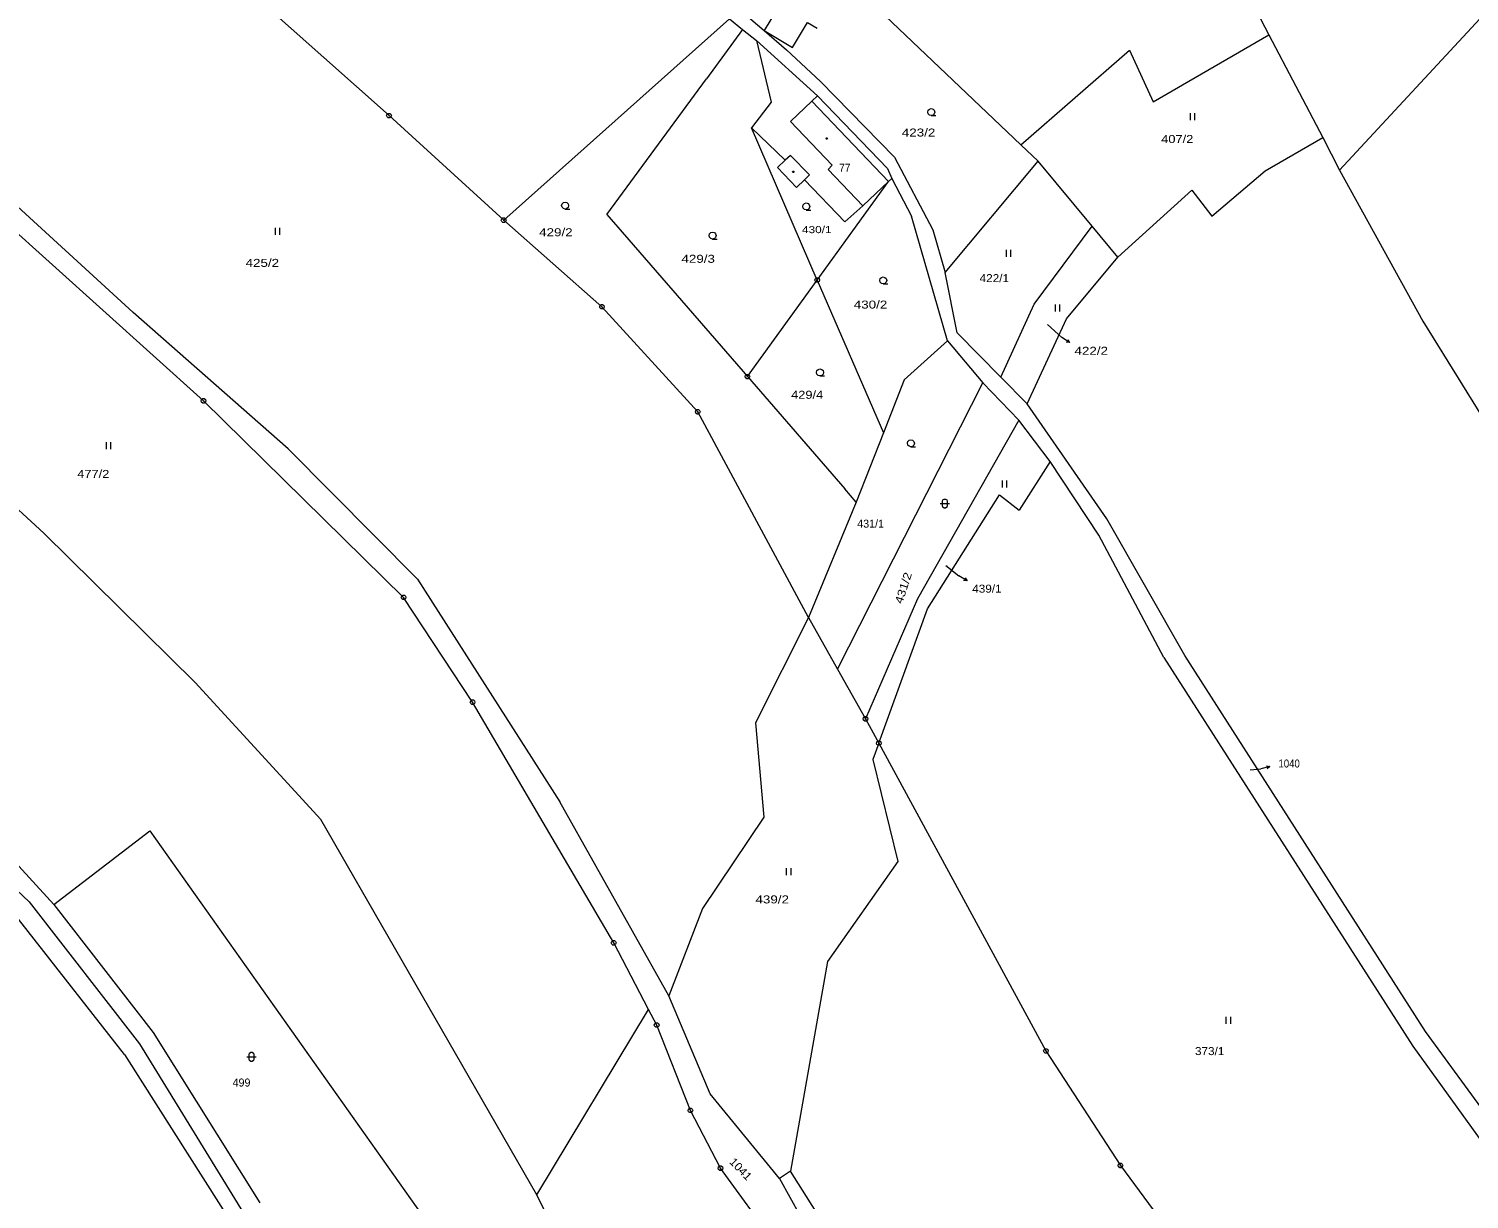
# Model space of a CAD drawing. Extents: x -687390 to -684106, y -954833 to -951648.
# Drawn here: x -686675.9 to -686369.8, y -953064 to -952815.4 of the extents above; entities that cross this region are included whole.
import ezdxf

# ---------------------------------------------------------------- set-up
doc = ezdxf.new("R2010")
doc.units = 0
doc.header["$LTSCALE"] = 0.68
for name, color, linetype, lineweight in [('1', 7, 'Continuous', 13), ('3', 7, 'Continuous', 13), ('4', 7, 'Continuous', 13), ('5', 7, 'Continuous', 13), ('7', 7, 'Continuous', 13), ('8', 7, 'Continuous', 13)]:
    doc.layers.add(name, color=color, linetype=linetype, lineweight=lineweight)
doc.layers.add('2', color=7, linetype='Continuous')

msp = doc.modelspace()

# ---------------------------------------------------------------- linework, layer by layer
at = {"layer": '1'}
for p, q in [((-686509.81, -952799.39), (-686519.6, -952815.68)), ((-686524.22, -952815.52), (-686531.9, -952825.99)), ((-686519.6, -952815.68), (-686514.85, -952819.8)), ((-686521.24, -952817.86), (-686508.32, -952829.6)), ((-686507.68, -952826.56), (-686514.85, -952819.8)), ((-686553.05, -952854.83), (-686531.9, -952825.99)), ((-686508.33, -952868.74), (-686522.33, -952836.4)), ((-686693.09, -952839.54), (-686653.72, -952875.6)), ((-686516.76, -952844.8), (-686515.14, -952843.29)), ((-686511.05, -952847.43), (-686502.5, -952856.37)), ((-686498.67, -952852.97), (-686493.17, -952847.8)), ((-686493.17, -952847.8), (-686492.46, -952847.13)), ((-686492.46, -952847.13), (-686488.32, -952855.19)), ((-686502.5, -952856.37), (-686498.67, -952852.97)), ((-686553.05, -952854.83), (-686523.18, -952889.26)), ((-686462.22, -952873.88), (-686449.89, -952857.3)), ((-686672.7, -952922.52), (-686738.23, -952862.13)), ((-686508.33, -952868.74), (-686494.26, -952901.21)), ((-686469.32, -952889.38), (-686462.22, -952873.88)), ((-686620.74, -952904.63), (-686653.72, -952875.6)), ((-686523.18, -952889.26), (-686502.49, -952913.07)), ((-686504.01, -952951.43), (-686473.18, -952890.6)), ((-686489.85, -952889.96), (-686494.26, -952901.21)), ((-686494.26, -952901.21), (-686500.04, -952915.93)), ((-686593.31, -952932.3), (-686620.74, -952904.63)), ((-686458.83, -952907.29), (-686465.43, -952917.64)), ((-686500.04, -952915.93), (-686502.49, -952913.07)), ((-686469.61, -952914.35), (-686465.43, -952917.64)), ((-686672.7, -952922.52), (-686640.52, -952954.27)), ((-686434.72, -952948.96), (-686448.54, -952922.97)), ((-686593.31, -952932.3), (-686563.07, -952979.58)), ((-686434.72, -952948.96), (-686381.78, -953031.54)), ((-686613.86, -952983.34), (-686640.52, -952954.27)), ((-686670.54, -953001.44), (-686696.66, -952973)), ((-686539.88, -953020.85), (-686563.07, -952979.58)), ((-686670.54, -953001.44), (-686650.19, -952985.77)), ((-686650.19, -952985.77), (-686584.91, -953077.81)), ((-686567.94, -953063.1), (-686544.19, -953023.73)), ((-686320.99, -953107.93), (-686379.12, -953028.38)), ((-686381.78, -953031.54), (-686358.91, -953063.3)), ((-686655.57, -953033.26), (-686630.63, -953072.46)), ((-686495.55, -953087.28), (-686514, -953058.06)), ((-686516.33, -953059.65), (-686511.96, -953067.55))]:
    msp.add_line(p, q, dxfattribs=at)
for points in [[(-686646.49, -952707.88), (-686543.29, -952795.55), (-686519.6, -952815.68)], [(-686695.55, -952748.71), (-686654.22, -952784.95), (-686599.33, -952833.8), (-686574.97, -952856.02)], [(-686397.36, -952845.42), (-686365.69, -952811.22), (-686368.52, -952807.17), (-686369.02, -952794.4), (-686360.88, -952785.09), (-686366.08, -952768.4)], [(-686453.59, -952771.6), (-686414.98, -952811.6), (-686412.39, -952816.64)], [(-686551.59, -953009.58), (-686581.57, -952958.44), (-686596.23, -952936.18), (-686638.74, -952894.41), (-686702.99, -952836.61), (-686720, -952820.76), (-686730.92, -952811.22), (-686750.22, -952797.63), (-686771.71, -952798.21), (-686764.24, -952793.45), (-686750.29, -952793.68), (-686755.86, -952788.44)], [(-686500.04, -952915.93), (-686510.19, -952940.46), (-686533.73, -952896.74), (-686554.09, -952874.42), (-686574.97, -952856.02), (-686527, -952813.23), (-686524.22, -952815.52)], [(-686519.6, -952815.68), (-686513.58, -952819.3), (-686510.38, -952813.98), (-686508.39, -952815.18)], [(-686461.39, -952843.48), (-686465.11, -952839.97), (-686493.92, -952812.62)], [(-686524.22, -952815.52), (-686521.24, -952817.86), (-686518.14, -952830.94), (-686522.33, -952836.4), (-686515.14, -952843.29)], [(-686465.11, -952839.97), (-686442.01, -952819.9), (-686436.94, -952830.9), (-686412.39, -952816.64), (-686400.9, -952838.46)], [(-686507.68, -952826.56), (-686491.9, -952842.65), (-686483.77, -952858.03), (-686481.13, -952867.13)], [(-686508.32, -952829.6), (-686493.42, -952845.05), (-686492.46, -952847.13)], [(-686444.44, -952863.85), (-686428.72, -952849.66), (-686424.51, -952855.14), (-686413.17, -952845.53), (-686400.9, -952838.46), (-686397.36, -952845.42)], [(-686516.76, -952844.8), (-686512.77, -952849.07), (-686511.05, -952847.43)], [(-686478.6, -952879.92), (-686481.13, -952867.13), (-686461.39, -952843.48)], [(-686444.44, -952863.85), (-686449.89, -952857.3), (-686461.39, -952843.48)], [(-686523.18, -952889.26), (-686508.33, -952868.74), (-686493.17, -952847.8)], [(-686397.36, -952845.42), (-686379.65, -952877.44), (-686354.39, -952918.28)], [(-686489.85, -952889.96), (-686480.65, -952881.64), (-686488.32, -952855.19)], [(-686379.12, -953028.38), (-686430.21, -952948.54), (-686446.81, -952919.48), (-686463.76, -952895.04), (-686455.41, -952876.97), (-686444.44, -952863.85)], [(-686463.76, -952895.04), (-686469.32, -952889.38), (-686478.6, -952879.92)], [(-686480.65, -952881.64), (-686473.18, -952890.6), (-686465.48, -952898.5)], [(-686465.48, -952898.5), (-686487.06, -952936.49), (-686498.08, -952961.98)], [(-686448.54, -952922.97), (-686458.83, -952907.29), (-686465.48, -952898.5)], [(-686495.25, -952967.14), (-686484.95, -952938.57), (-686469.61, -952914.35)], [(-686744.67, -952933.19), (-686724.45, -952954.91), (-686675.78, -953000.89), (-686652.38, -953031), (-686618.65, -953085.9), (-686604.76, -953115.49), (-686593.43, -953134.24)], [(-686510.19, -952940.46), (-686521.45, -952962.85), (-686519.67, -952982.87), (-686532.76, -953002.28), (-686539.88, -953020.85)], [(-686510.19, -952940.46), (-686504.01, -952951.43), (-686498.08, -952961.98)], [(-686655.57, -953033.26), (-686679.35, -953002.91), (-686725.64, -952957.15)], [(-686498.08, -952961.98), (-686495.25, -952967.14), (-686459.74, -953032.55), (-686443.92, -953056.89), (-686425.27, -953082.18), (-686401.26, -953112.58), (-686367.6, -953151.83), (-686353.01, -953164.57)], [(-686495.25, -952967.14), (-686496.51, -952970.6), (-686491.22, -952992.29), (-686506.18, -953013.5), (-686514, -953058.06), (-686516.33, -953059.65), (-686531.12, -953041.67), (-686539.88, -953020.85)], [(-686566.44, -953066.15), (-686567.94, -953063.1), (-686613.86, -952983.34)], [(-686670.54, -953001.44), (-686649.45, -953028.64), (-686626.76, -953064.78)], [(-686542.46, -953027.04), (-686544.19, -953023.73), (-686551.59, -953009.58)], [(-686252.58, -953389.33), (-686292.75, -953324.92), (-686302.57, -953310.07), (-686336.76, -953268.21), (-686375.07, -953232.58), (-686400.17, -953211.88), (-686416.48, -953192.52), (-686437.08, -953164.4), (-686477, -953119.5), (-686503.23, -953091.93), (-686517.39, -953073.32), (-686528.9, -953057.45), (-686535.29, -953045.19), (-686542.46, -953027.04)]]:
    msp.add_lwpolyline(points, dxfattribs=at)
at = {"layer": '3'}
for p, q in [((-686429.1, -952833.24), (-686429.1, -952834.74)), ((-686428.1, -952834.74), (-686428.1, -952833.24)), ((-686623.55, -952857.63), (-686623.55, -952859.13)), ((-686622.55, -952859.13), (-686622.55, -952857.63)), ((-686468.22, -952862.28), (-686468.22, -952863.78)), ((-686467.22, -952863.78), (-686467.22, -952862.28)), ((-686457.81, -952873.93), (-686457.81, -952875.43)), ((-686456.81, -952875.43), (-686456.81, -952873.93)), ((-686659.44, -952903.17), (-686659.44, -952904.67)), ((-686658.44, -952904.67), (-686658.44, -952903.17)), ((-686469.03, -952911.31), (-686469.03, -952912.81)), ((-686468.03, -952912.81), (-686468.03, -952911.31)), ((-686514.92, -952993.7), (-686514.92, -952995.2)), ((-686513.92, -952995.2), (-686513.92, -952993.7)), ((-686421.49, -953025.3), (-686421.49, -953026.8)), ((-686420.49, -953026.8), (-686420.49, -953025.3))]:
    msp.add_line(p, q, dxfattribs=at)
for points in [[(-686484.1, -952833.78), (-686484.48, -952833.68), (-686484.75, -952833.41), (-686484.85, -952833.04), (-686484.75, -952832.67), (-686484.48, -952832.4), (-686484.11, -952832.3), (-686483.74, -952832.4), (-686483.47, -952832.67), (-686483.37, -952833.05), (-686483.47, -952833.43), (-686483.74, -952833.7), (-686484.12, -952833.8), (-686483.12, -952833.8)], [(-686561.91, -952853.64), (-686562.29, -952853.54), (-686562.56, -952853.27), (-686562.66, -952852.9), (-686562.56, -952852.53), (-686562.29, -952852.26), (-686561.92, -952852.16), (-686561.55, -952852.26), (-686561.28, -952852.53), (-686561.18, -952852.91), (-686561.28, -952853.29), (-686561.55, -952853.56), (-686561.93, -952853.66), (-686560.93, -952853.66)], [(-686510.66, -952853.84), (-686511.04, -952853.74), (-686511.31, -952853.47), (-686511.41, -952853.1), (-686511.31, -952852.73), (-686511.04, -952852.46), (-686510.67, -952852.36), (-686510.3, -952852.46), (-686510.03, -952852.73), (-686509.93, -952853.11), (-686510.03, -952853.49), (-686510.3, -952853.76), (-686510.68, -952853.86), (-686509.68, -952853.86)], [(-686530.57, -952860.02), (-686530.95, -952859.92), (-686531.22, -952859.65), (-686531.32, -952859.28), (-686531.22, -952858.91), (-686530.95, -952858.64), (-686530.58, -952858.54), (-686530.21, -952858.64), (-686529.94, -952858.91), (-686529.84, -952859.29), (-686529.94, -952859.67), (-686530.21, -952859.94), (-686530.59, -952860.04), (-686529.59, -952860.04)], [(-686494.31, -952869.55), (-686494.69, -952869.45), (-686494.96, -952869.18), (-686495.06, -952868.81), (-686494.96, -952868.44), (-686494.69, -952868.17), (-686494.32, -952868.07), (-686493.95, -952868.17), (-686493.68, -952868.44), (-686493.58, -952868.82), (-686493.68, -952869.2), (-686493.95, -952869.47), (-686494.33, -952869.57), (-686493.33, -952869.57)], [(-686507.75, -952889.09), (-686508.13, -952888.99), (-686508.4, -952888.72), (-686508.5, -952888.35), (-686508.4, -952887.98), (-686508.13, -952887.71), (-686507.76, -952887.61), (-686507.39, -952887.71), (-686507.12, -952887.98), (-686507.02, -952888.36), (-686507.12, -952888.74), (-686507.39, -952889.01), (-686507.77, -952889.11), (-686506.77, -952889.11)], [(-686488.43, -952904.16), (-686488.81, -952904.06), (-686489.08, -952903.79), (-686489.18, -952903.42), (-686489.08, -952903.05), (-686488.81, -952902.78), (-686488.44, -952902.68), (-686488.07, -952902.78), (-686487.8, -952903.05), (-686487.7, -952903.43), (-686487.8, -952903.81), (-686488.07, -952904.08), (-686488.45, -952904.18), (-686487.45, -952904.18)], [(-686482.25, -952916.23), (-686480.98, -952916.23), (-686480.25, -952916.23)], [(-686629.56, -953033.8), (-686628.29, -953033.8), (-686627.56, -953033.8)]]:
    msp.add_lwpolyline(points, dxfattribs=at)
for points in [[(-686481.75, -952915.73), (-686481.65, -952915.44), (-686481.4, -952915.26), (-686481.09, -952915.26), (-686480.84, -952915.44), (-686480.74, -952915.73), (-686480.74, -952916.73), (-686480.84, -952917.02), (-686481.09, -952917.2), (-686481.4, -952917.2), (-686481.65, -952917.02), (-686481.75, -952916.73)], [(-686629.06, -953033.3), (-686628.96, -953033.01), (-686628.71, -953032.83), (-686628.4, -953032.83), (-686628.15, -953033.01), (-686628.05, -953033.3), (-686628.05, -953034.3), (-686628.15, -953034.59), (-686628.4, -953034.77), (-686628.71, -953034.77), (-686628.96, -953034.59), (-686629.06, -953034.3)]]:
    msp.add_lwpolyline(points, close=True, dxfattribs=at)
at = {"layer": '4'}
for p, q in [((-686509.46, -952830.7), (-686514.01, -952835.05)), ((-686508.32, -952829.6), (-686509.46, -952830.7)), ((-686493.17, -952847.8), (-686509.46, -952830.7)), ((-686514.01, -952835.05), (-686505.15, -952844.35)), ((-686511.05, -952847.43), (-686509.99, -952846.41))]:
    msp.add_line(p, q, dxfattribs=at)
for points in [[(-686509.99, -952846.41), (-686514.01, -952842.24), (-686515.14, -952843.29)], [(-686505.15, -952844.35), (-686506.04, -952845.22), (-686498.67, -952852.97)]]:
    msp.add_lwpolyline(points, dxfattribs=at)
at = {"layer": '5'}
for points in [[(-686506.23, -952838.51), (-686506.14, -952838.66), (-686506.23, -952838.81), (-686506.41, -952838.81), (-686506.5, -952838.66), (-686506.41, -952838.51)], [(-686513.34, -952845.57), (-686513.25, -952845.72), (-686513.34, -952845.87), (-686513.52, -952845.87), (-686513.61, -952845.72), (-686513.52, -952845.57)]]:
    msp.add_lwpolyline(points, close=True, dxfattribs=at)
at = {"layer": '7'}
for p, q in [((-686459.41, -952878.15), (-686456.37, -952880.91)), ((-686454.706, -952882.037), (-686456.37, -952880.91)), ((-686481.03, -952929.42), (-686478.26, -952931.61)), ((-686476.521, -952932.618), (-686478.26, -952931.61)), ((-686416.32, -952972.78), (-686414.12, -952972.58)), ((-686412.164, -952972.117), (-686414.12, -952972.58))]:
    msp.add_line(p, q, dxfattribs=at)
for points in [[(-686455.073, -952881.384), (-686454.706, -952882.037), (-686455.448, -952881.939)], [(-686476.933, -952931.992), (-686476.521, -952932.618), (-686477.269, -952932.572)], [(-686412.893, -952971.945), (-686412.164, -952972.117), (-686412.739, -952972.597)]]:
    msp.add_lwpolyline(points, dxfattribs=at)
at = {"layer": '8'}
for p, q in [((-686599.45, -952833.8), (-686599.21, -952833.8)), ((-686575.09, -952856.02), (-686574.85, -952856.02)), ((-686508.45, -952868.74), (-686508.21, -952868.74)), ((-686554.21, -952874.42), (-686553.97, -952874.42)), ((-686523.3, -952889.26), (-686523.06, -952889.26)), ((-686638.86, -952894.41), (-686638.62, -952894.41)), ((-686533.85, -952896.74), (-686533.61, -952896.74)), ((-686596.35, -952936.18), (-686596.11, -952936.18)), ((-686581.69, -952958.44), (-686581.45, -952958.44)), ((-686498.2, -952961.98), (-686497.96, -952961.98)), ((-686495.37, -952967.14), (-686495.13, -952967.14)), ((-686551.71, -953009.58), (-686551.47, -953009.58)), ((-686542.58, -953027.04), (-686542.34, -953027.04)), ((-686459.86, -953032.55), (-686459.62, -953032.55)), ((-686535.41, -953045.19), (-686535.17, -953045.19)), ((-686529.02, -953057.45), (-686528.78, -953057.45)), ((-686444.04, -953056.89), (-686443.8, -953056.89))]:
    msp.add_line(p, q, dxfattribs=at)
for points in [[(-686599.18, -952833.32), (-686598.93, -952833.5), (-686598.83, -952833.79), (-686598.93, -952834.08), (-686599.18, -952834.26), (-686599.49, -952834.26), (-686599.74, -952834.08), (-686599.84, -952833.79), (-686599.74, -952833.5), (-686599.49, -952833.32)], [(-686574.82, -952855.54), (-686574.57, -952855.72), (-686574.47, -952856.01), (-686574.57, -952856.3), (-686574.82, -952856.48), (-686575.13, -952856.48), (-686575.38, -952856.3), (-686575.48, -952856.01), (-686575.38, -952855.72), (-686575.13, -952855.54)], [(-686508.18, -952868.26), (-686507.93, -952868.44), (-686507.83, -952868.73), (-686507.93, -952869.02), (-686508.18, -952869.2), (-686508.49, -952869.2), (-686508.74, -952869.02), (-686508.84, -952868.73), (-686508.74, -952868.44), (-686508.49, -952868.26)], [(-686553.94, -952873.94), (-686553.69, -952874.12), (-686553.59, -952874.41), (-686553.69, -952874.7), (-686553.94, -952874.88), (-686554.25, -952874.88), (-686554.5, -952874.7), (-686554.6, -952874.41), (-686554.5, -952874.12), (-686554.25, -952873.94)], [(-686523.03, -952888.78), (-686522.78, -952888.96), (-686522.68, -952889.25), (-686522.78, -952889.54), (-686523.03, -952889.72), (-686523.34, -952889.72), (-686523.59, -952889.54), (-686523.69, -952889.25), (-686523.59, -952888.96), (-686523.34, -952888.78)], [(-686638.59, -952893.93), (-686638.34, -952894.11), (-686638.24, -952894.4), (-686638.34, -952894.69), (-686638.59, -952894.87), (-686638.9, -952894.87), (-686639.15, -952894.69), (-686639.25, -952894.4), (-686639.15, -952894.11), (-686638.9, -952893.93)], [(-686533.58, -952896.26), (-686533.33, -952896.44), (-686533.23, -952896.73), (-686533.33, -952897.02), (-686533.58, -952897.2), (-686533.89, -952897.2), (-686534.14, -952897.02), (-686534.24, -952896.73), (-686534.14, -952896.44), (-686533.89, -952896.26)], [(-686596.08, -952935.7), (-686595.83, -952935.88), (-686595.73, -952936.17), (-686595.83, -952936.46), (-686596.08, -952936.64), (-686596.39, -952936.64), (-686596.64, -952936.46), (-686596.74, -952936.17), (-686596.64, -952935.88), (-686596.39, -952935.7)], [(-686581.42, -952957.96), (-686581.17, -952958.14), (-686581.07, -952958.43), (-686581.17, -952958.72), (-686581.42, -952958.9), (-686581.73, -952958.9), (-686581.98, -952958.72), (-686582.08, -952958.43), (-686581.98, -952958.14), (-686581.73, -952957.96)], [(-686497.93, -952961.5), (-686497.68, -952961.68), (-686497.58, -952961.97), (-686497.68, -952962.26), (-686497.93, -952962.44), (-686498.24, -952962.44), (-686498.49, -952962.26), (-686498.59, -952961.97), (-686498.49, -952961.68), (-686498.24, -952961.5)], [(-686495.1, -952966.66), (-686494.85, -952966.84), (-686494.75, -952967.13), (-686494.85, -952967.42), (-686495.1, -952967.6), (-686495.41, -952967.6), (-686495.66, -952967.42), (-686495.76, -952967.13), (-686495.66, -952966.84), (-686495.41, -952966.66)], [(-686551.44, -953009.1), (-686551.19, -953009.28), (-686551.09, -953009.57), (-686551.19, -953009.86), (-686551.44, -953010.04), (-686551.75, -953010.04), (-686552, -953009.86), (-686552.1, -953009.57), (-686552, -953009.28), (-686551.75, -953009.1)], [(-686542.31, -953026.56), (-686542.06, -953026.74), (-686541.96, -953027.03), (-686542.06, -953027.32), (-686542.31, -953027.5), (-686542.62, -953027.5), (-686542.87, -953027.32), (-686542.97, -953027.03), (-686542.87, -953026.74), (-686542.62, -953026.56)], [(-686459.59, -953032.07), (-686459.34, -953032.25), (-686459.24, -953032.54), (-686459.34, -953032.83), (-686459.59, -953033.01), (-686459.9, -953033.01), (-686460.15, -953032.83), (-686460.25, -953032.54), (-686460.15, -953032.25), (-686459.9, -953032.07)], [(-686535.14, -953044.71), (-686534.89, -953044.89), (-686534.79, -953045.18), (-686534.89, -953045.47), (-686535.14, -953045.65), (-686535.45, -953045.65), (-686535.7, -953045.47), (-686535.8, -953045.18), (-686535.7, -953044.89), (-686535.45, -953044.71)], [(-686528.75, -953056.97), (-686528.5, -953057.15), (-686528.4, -953057.44), (-686528.5, -953057.73), (-686528.75, -953057.91), (-686529.06, -953057.91), (-686529.31, -953057.73), (-686529.41, -953057.44), (-686529.31, -953057.15), (-686529.06, -953056.97)], [(-686443.77, -953056.41), (-686443.52, -953056.59), (-686443.42, -953056.88), (-686443.52, -953057.17), (-686443.77, -953057.35), (-686444.08, -953057.35), (-686444.33, -953057.17), (-686444.43, -953056.88), (-686444.33, -953056.59), (-686444.08, -953056.41)]]:
    msp.add_lwpolyline(points, close=True, dxfattribs=at)

# ---------------------------------------------------------------- texts
at = {"layer": '2'}
for s, height, width, p in [('423/2', 1.7, 1.25, (-686490.365, -952838.24)), ('407/2', 1.7, 1.2, (-686435.255, -952839.62)), ('77', 1.7, 0.95, (-686503.695, -952845.73)), ('429/2', 1.7, 1.25, (-686567.435, -952859.43)), ('430/1', 1.5, 1.25, (-686511.581, -952858.77)), ('425/2', 1.7, 1.25, (-686629.815, -952865.94)), ('429/3', 1.7, 1.25, (-686537.195, -952865.07)), ('422/1', 1.7, 1.1, (-686473.845, -952869.18)), ('430/2', 1.7, 1.25, (-686500.575, -952874.8)), ('422/2', 0.1, 1.25, (-686459.382, -952878.15)), ('429/4', 1.7, 1.2, (-686513.905, -952893.96)), ('477/2', 1.7, 1.2, (-686665.595, -952910.78)), ('439/1', 0.1, 1.1, (-686481.002, -952929.42)), ('1040', 0.1, 0.9, (-686416.274, -952972.78)), ('439/2', 1.7, 1.25, (-686521.465, -953001.19)), ('373/1', 1.7, 1.1, (-686428.085, -953033.42))]:
    msp.add_text(s, height=height, dxfattribs=dict(at, width=width)).set_placement(p)
for s, p in [('431/1', (-686499.845, -952921.34)), ('499', (-686632.575, -953040.1))]:
    msp.add_text(s, height=1.7, dxfattribs=at).set_placement(p)
for s, rotation, width, p in [('431/2', 72.135, 1.2, (-686490.294, -952937.668)), ('1041', 314.038, 1.1, (-686527.144, -953056.225))]:
    msp.add_text(s, height=1.7, rotation=rotation, dxfattribs=dict(at, width=width)).set_placement(p)
at = {"layer": '7'}
for s, width, p in [('422/2', 1.25, (-686453.675, -952884.62)), ('439/1', 1.1, (-686475.415, -952935.16)), ('1040', 0.9, (-686410.345, -952972.31))]:
    msp.add_text(s, height=1.7, dxfattribs=dict(at, width=width)).set_placement(p)

doc.saveas('drawing.dxf')
